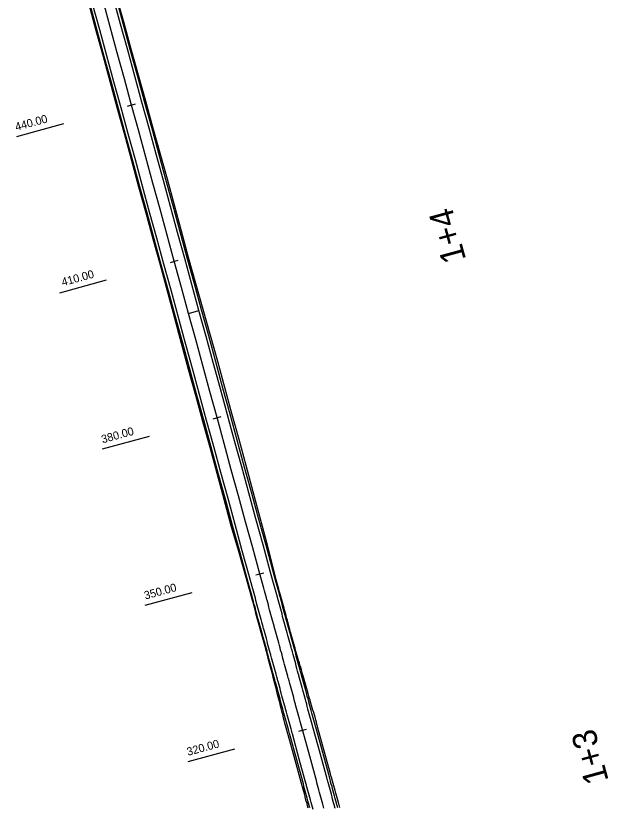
# Model space of a CAD drawing. Extents: x -550605 to -538780, y -1102367 to -1093705.
# Drawn here: x -547439.5 to -547329.7, y -1100950.2 to -1100803.7 of the extents above; entities that cross this region are included whole.
import ezdxf

# ---------------------------------------------------------------- set-up
doc = ezdxf.new("R2010")
doc.units = 0
for name, color, linetype in [('SIT - hrany vozovky', 7, 'Continuous'), ('SIT - osa cesty', 7, 'Continuous'), ('SIT - paty násypů', 7, 'Continuous'), ('SIT - staničení po 100m', 7, 'Continuous'), ('SIT - staničení po 30m', 7, 'Continuous')]:
    doc.layers.add(name, color=color, linetype=linetype)

msp = doc.modelspace()

# ---------------------------------------------------------------- linework, layer by layer
at = {"layer": 'SIT - hrany vozovky'}
for points in [[(-547380.29, -1100950.47), (-547380.41, -1100950.03), (-547380.45, -1100949.88), (-547380.53, -1100949.58), (-547380.65, -1100949.14), (-547380.77, -1100948.7), (-547380.89, -1100948.26), (-547381.01, -1100947.82), (-547381.13, -1100947.37), (-547381.26, -1100946.93), (-547381.38, -1100946.49), (-547381.5, -1100946.05), (-547381.62, -1100945.61), (-547381.74, -1100945.17), (-547381.77, -1100945.06), (-547381.86, -1100944.72), (-547381.98, -1100944.28), (-547383.09, -1100940.23), (-547384.37, -1100935.55), (-547384.41, -1100935.41), (-547384.49, -1100935.11), (-547384.61, -1100934.67), (-547384.73, -1100934.23), (-547384.85, -1100933.79), (-547384.97, -1100933.35), (-547385.09, -1100932.91), (-547385.22, -1100932.47), (-547385.34, -1100932.03), (-547385.46, -1100931.59), (-547385.58, -1100931.15), (-547385.7, -1100930.71), (-547385.73, -1100930.59), (-547385.82, -1100930.27), (-547385.94, -1100929.83), (-547386.06, -1100929.39), (-547386.18, -1100928.95), (-547386.3, -1100928.51), (-547386.42, -1100928.07), (-547386.54, -1100927.63), (-547386.66, -1100927.19), (-547386.78, -1100926.75), (-547386.9, -1100926.31), (-547387.02, -1100925.87), (-547387.05, -1100925.77), (-547387.14, -1100925.43), (-547387.26, -1100924.99), (-547387.38, -1100924.55), (-547387.5, -1100924.11), (-547387.62, -1100923.67), (-547387.74, -1100923.23), (-547387.86, -1100922.79), (-547387.98, -1100922.35), (-547388.1, -1100921.91), (-547388.23, -1100921.47), (-547388.35, -1100921.03), (-547388.37, -1100920.94), (-547388.47, -1100920.59), (-547388.59, -1100920.15), (-547388.71, -1100919.71), (-547388.83, -1100919.27), (-547388.95, -1100918.83), (-547389.07, -1100918.39), (-547389.19, -1100917.95), (-547389.31, -1100917.51), (-547389.43, -1100917.07), (-547389.55, -1100916.63), (-547389.67, -1100916.19), (-547389.69, -1100916.12), (-547389.79, -1100915.75), (-547389.91, -1100915.31), (-547390.03, -1100914.87), (-547390.15, -1100914.43), (-547390.27, -1100913.99), (-547390.39, -1100913.55), (-547390.51, -1100913.11), (-547390.63, -1100912.67), (-547390.75, -1100912.23), (-547390.87, -1100911.79), (-547390.99, -1100911.35), (-547391.01, -1100911.3), (-547391.12, -1100910.91), (-547391.24, -1100910.47), (-547391.36, -1100910.03), (-547391.48, -1100909.59), (-547391.6, -1100909.15), (-547391.72, -1100908.71), (-547391.84, -1100908.27), (-547392.33, -1100906.48), (-547393.65, -1100901.65), (-547394.97, -1100896.83), (-547396.29, -1100892.01), (-547397.61, -1100887.18), (-547398.93, -1100882.36), (-547400.25, -1100877.54), (-547401.57, -1100872.72), (-547402.89, -1100867.89), (-547404.21, -1100863.07), (-547405.53, -1100858.25), (-547406.85, -1100853.43), (-547408.17, -1100848.6), (-547409.49, -1100843.78), (-547410.81, -1100838.96), (-547412.13, -1100834.14), (-547413.45, -1100829.31), (-547414.77, -1100824.49), (-547416.09, -1100819.67), (-547417.41, -1100814.85), (-547418.73, -1100810.02), (-547420.05, -1100805.2), (-547421.37, -1100800.38)], [(-547379.81, -1100950.34), (-547379.93, -1100949.89), (-547379.97, -1100949.75), (-547380.05, -1100949.45), (-547380.17, -1100949.01), (-547380.29, -1100948.57), (-547380.41, -1100948.13), (-547380.53, -1100947.68), (-547380.65, -1100947.24), (-547380.77, -1100946.8), (-547380.89, -1100946.36), (-547381.02, -1100945.92), (-547381.14, -1100945.48), (-547381.26, -1100945.03), (-547381.29, -1100944.92), (-547381.38, -1100944.59), (-547381.5, -1100944.15), (-547382.61, -1100940.1), (-547383.89, -1100935.41), (-547383.93, -1100935.28), (-547384.01, -1100934.97), (-547384.13, -1100934.53), (-547384.25, -1100934.09), (-547384.37, -1100933.65), (-547384.49, -1100933.21), (-547384.61, -1100932.77), (-547384.73, -1100932.33), (-547384.85, -1100931.89), (-547384.97, -1100931.45), (-547385.09, -1100931.01), (-547385.21, -1100930.57), (-547385.25, -1100930.46), (-547385.33, -1100930.14), (-547385.46, -1100929.7), (-547385.58, -1100929.26), (-547385.7, -1100928.82), (-547385.82, -1100928.38), (-547385.94, -1100927.94), (-547386.06, -1100927.5), (-547386.18, -1100927.06), (-547386.3, -1100926.62), (-547386.42, -1100926.18), (-547386.54, -1100925.74), (-547386.57, -1100925.63), (-547386.66, -1100925.3), (-547386.78, -1100924.86), (-547386.9, -1100924.42), (-547387.02, -1100923.98), (-547387.14, -1100923.54), (-547387.26, -1100923.1), (-547387.38, -1100922.66), (-547387.5, -1100922.22), (-547387.62, -1100921.78), (-547387.74, -1100921.34), (-547387.86, -1100920.9), (-547387.89, -1100920.81), (-547387.98, -1100920.46), (-547388.1, -1100920.02), (-547388.22, -1100919.58), (-547388.35, -1100919.14), (-547388.47, -1100918.7), (-547388.59, -1100918.26), (-547388.71, -1100917.82), (-547388.83, -1100917.38), (-547388.95, -1100916.94), (-547389.07, -1100916.5), (-547389.19, -1100916.06), (-547389.21, -1100915.99), (-547389.31, -1100915.62), (-547389.43, -1100915.18), (-547389.55, -1100914.74), (-547389.67, -1100914.3), (-547389.79, -1100913.86), (-547389.91, -1100913.42), (-547390.03, -1100912.98), (-547390.15, -1100912.54), (-547390.27, -1100912.1), (-547390.39, -1100911.66), (-547390.51, -1100911.22), (-547390.53, -1100911.17), (-547390.63, -1100910.78), (-547390.75, -1100910.34), (-547390.87, -1100909.9), (-547390.99, -1100909.46), (-547391.11, -1100909.02), (-547391.24, -1100908.58), (-547391.36, -1100908.14), (-547391.85, -1100906.34), (-547393.17, -1100901.52), (-547394.49, -1100896.7), (-547395.81, -1100891.88), (-547397.13, -1100887.05), (-547398.45, -1100882.23), (-547399.77, -1100877.41), (-547401.09, -1100872.59), (-547402.41, -1100867.76), (-547403.73, -1100862.94), (-547405.05, -1100858.12), (-547406.37, -1100853.29), (-547407.69, -1100848.47), (-547409.01, -1100843.65), (-547410.33, -1100838.83), (-547411.65, -1100834), (-547412.97, -1100829.18), (-547414.29, -1100824.36), (-547415.61, -1100819.54), (-547416.93, -1100814.71), (-547418.25, -1100809.89), (-547419.57, -1100805.07), (-547420.89, -1100800.25)], [(-547384.99, -1100950.33), (-547385.11, -1100949.89), (-547385.23, -1100949.45), (-547385.35, -1100949), (-547385.48, -1100948.56), (-547385.6, -1100948.12), (-547385.72, -1100947.68), (-547385.84, -1100947.24), (-547385.96, -1100946.8), (-547386.08, -1100946.35), (-547386.11, -1100946.24), (-547386.2, -1100945.91), (-547386.32, -1100945.47), (-547387.43, -1100941.42), (-547388.71, -1100936.73), (-547388.75, -1100936.6), (-547388.83, -1100936.29), (-547388.95, -1100935.85), (-547389.07, -1100935.41), (-547389.19, -1100934.97), (-547389.31, -1100934.53), (-547389.43, -1100934.09), (-547389.56, -1100933.65), (-547389.68, -1100933.21), (-547389.8, -1100932.77), (-547389.92, -1100932.33), (-547390.04, -1100931.89), (-547390.07, -1100931.78), (-547390.16, -1100931.45), (-547390.28, -1100931.01), (-547390.4, -1100930.57), (-547390.52, -1100930.14), (-547390.64, -1100929.7), (-547390.76, -1100929.26), (-547390.88, -1100928.82), (-547391, -1100928.38), (-547391.12, -1100927.94), (-547391.24, -1100927.5), (-547391.36, -1100927.06), (-547391.39, -1100926.95), (-547391.48, -1100926.62), (-547391.6, -1100926.18), (-547391.72, -1100925.74), (-547391.84, -1100925.3), (-547391.96, -1100924.86), (-547392.08, -1100924.42), (-547392.2, -1100923.98), (-547392.32, -1100923.54), (-547392.45, -1100923.1), (-547392.57, -1100922.66), (-547392.69, -1100922.22), (-547392.71, -1100922.13), (-547392.81, -1100921.78), (-547392.93, -1100921.34), (-547393.05, -1100920.9), (-547393.17, -1100920.46), (-547393.29, -1100920.02), (-547393.41, -1100919.58), (-547393.53, -1100919.14), (-547393.65, -1100918.7), (-547393.77, -1100918.26), (-547393.89, -1100917.82), (-547394.01, -1100917.38), (-547394.03, -1100917.31), (-547394.13, -1100916.94), (-547394.25, -1100916.5), (-547394.37, -1100916.06), (-547394.49, -1100915.62), (-547394.61, -1100915.18), (-547394.73, -1100914.74), (-547394.85, -1100914.3), (-547394.97, -1100913.86), (-547395.09, -1100913.42), (-547395.21, -1100912.98), (-547395.34, -1100912.54), (-547395.35, -1100912.49), (-547395.46, -1100912.1), (-547395.58, -1100911.66), (-547395.7, -1100911.22), (-547395.82, -1100910.78), (-547395.94, -1100910.34), (-547396.06, -1100909.9), (-547396.18, -1100909.46), (-547396.67, -1100907.66), (-547397.99, -1100902.84), (-547399.31, -1100898.02), (-547400.63, -1100893.2), (-547401.95, -1100888.37), (-547403.27, -1100883.55), (-547404.59, -1100878.73), (-547405.91, -1100873.9), (-547407.23, -1100869.08), (-547408.55, -1100864.26), (-547409.87, -1100859.44), (-547411.19, -1100854.61), (-547412.51, -1100849.79), (-547413.83, -1100844.97), (-547415.15, -1100840.15), (-547416.47, -1100835.32), (-547417.79, -1100830.5), (-547419.11, -1100825.68), (-547420.43, -1100820.86), (-547421.75, -1100816.03), (-547423.07, -1100811.21), (-547424.39, -1100806.39), (-547425.71, -1100801.57)], [(-547384.39, -1100950.64), (-547384.51, -1100950.2), (-547384.63, -1100949.76), (-547384.75, -1100949.31), (-547384.87, -1100948.87), (-547384.99, -1100948.43), (-547385.11, -1100947.99), (-547385.23, -1100947.55), (-547385.36, -1100947.11), (-547385.48, -1100946.66), (-547385.6, -1100946.22), (-547385.63, -1100946.11), (-547385.72, -1100945.78), (-547385.84, -1100945.34), (-547386.95, -1100941.29), (-547388.23, -1100936.6), (-547388.27, -1100936.47), (-547388.35, -1100936.16), (-547388.47, -1100935.72), (-547388.59, -1100935.28), (-547388.71, -1100934.84), (-547388.83, -1100934.4), (-547388.95, -1100933.96), (-547389.07, -1100933.52), (-547389.19, -1100933.08), (-547389.31, -1100932.64), (-547389.43, -1100932.2), (-547389.55, -1100931.76), (-547389.59, -1100931.64), (-547389.68, -1100931.32), (-547389.8, -1100930.88), (-547389.92, -1100930.44), (-547390.04, -1100930), (-547390.16, -1100929.56), (-547390.28, -1100929.12), (-547390.4, -1100928.68), (-547390.52, -1100928.24), (-547390.64, -1100927.8), (-547390.76, -1100927.36), (-547390.88, -1100926.92), (-547390.91, -1100926.82), (-547391, -1100926.48), (-547391.12, -1100926.04), (-547391.24, -1100925.6), (-547391.36, -1100925.16), (-547391.48, -1100924.72), (-547391.6, -1100924.28), (-547391.72, -1100923.84), (-547391.84, -1100923.4), (-547391.96, -1100922.96), (-547392.08, -1100922.52), (-547392.2, -1100922.08), (-547392.23, -1100922), (-547392.32, -1100921.64), (-547392.44, -1100921.2), (-547392.57, -1100920.76), (-547392.69, -1100920.32), (-547392.81, -1100919.88), (-547392.93, -1100919.44), (-547393.05, -1100919), (-547393.17, -1100918.56), (-547393.29, -1100918.12), (-547393.41, -1100917.68), (-547393.53, -1100917.24), (-547393.55, -1100917.18), (-547393.65, -1100916.8), (-547393.77, -1100916.36), (-547393.89, -1100915.92), (-547394.01, -1100915.48), (-547394.13, -1100915.04), (-547394.25, -1100914.6), (-547394.37, -1100914.16), (-547394.49, -1100913.72), (-547394.61, -1100913.28), (-547394.73, -1100912.84), (-547394.85, -1100912.4), (-547394.87, -1100912.35), (-547394.97, -1100911.96), (-547395.09, -1100911.52), (-547395.21, -1100911.08), (-547395.33, -1100910.64), (-547395.46, -1100910.21), (-547395.58, -1100909.77), (-547395.7, -1100909.33), (-547396.19, -1100907.53), (-547397.51, -1100902.71), (-547398.83, -1100897.89), (-547400.15, -1100893.06), (-547401.47, -1100888.24), (-547402.79, -1100883.42), (-547404.11, -1100878.6), (-547405.43, -1100873.77), (-547406.75, -1100868.95), (-547408.07, -1100864.13), (-547409.39, -1100859.31), (-547410.71, -1100854.48), (-547412.03, -1100849.66), (-547413.35, -1100844.84), (-547414.67, -1100840.01), (-547415.99, -1100835.19), (-547417.31, -1100830.37), (-547418.63, -1100825.55), (-547419.95, -1100820.72), (-547421.27, -1100815.9), (-547422.59, -1100811.08), (-547423.91, -1100806.26), (-547425.23, -1100801.43)]]:
    msp.add_lwpolyline(points, dxfattribs=at)
at = {"layer": 'SIT - osa cesty'}
msp.add_lwpolyline([(-547382.38, -1100950.41), (-547382.46, -1100950.11), (-547382.58, -1100949.67), (-547382.7, -1100949.23), (-547382.82, -1100948.79), (-547382.94, -1100948.34), (-547383.06, -1100947.9), (-547383.18, -1100947.46), (-547383.31, -1100947.02), (-547383.43, -1100946.58), (-547383.55, -1100946.14), (-547383.67, -1100945.69), (-547383.7, -1100945.58), (-547383.79, -1100945.25), (-547383.91, -1100944.81), (-547385.02, -1100940.76), (-547386.3, -1100936.07), (-547386.34, -1100935.94), (-547386.42, -1100935.63), (-547386.54, -1100935.19), (-547386.66, -1100934.75), (-547386.78, -1100934.31), (-547386.9, -1100933.87), (-547387.02, -1100933.43), (-547387.14, -1100932.99), (-547387.26, -1100932.55), (-547387.38, -1100932.11), (-547387.51, -1100931.67), (-547387.63, -1100931.23), (-547387.66, -1100931.12), (-547387.75, -1100930.79), (-547387.87, -1100930.35), (-547387.99, -1100929.92), (-547388.11, -1100929.48), (-547388.23, -1100929.04), (-547388.35, -1100928.6), (-547388.47, -1100928.16), (-547388.59, -1100927.72), (-547388.71, -1100927.28), (-547388.83, -1100926.84), (-547388.95, -1100926.4), (-547388.98, -1100926.29), (-547389.07, -1100925.96), (-547389.19, -1100925.52), (-547389.31, -1100925.08), (-547389.43, -1100924.64), (-547389.55, -1100924.2), (-547389.67, -1100923.76), (-547389.79, -1100923.32), (-547389.91, -1100922.88), (-547390.03, -1100922.44), (-547390.15, -1100922), (-547390.27, -1100921.56), (-547390.3, -1100921.47), (-547390.4, -1100921.12), (-547390.52, -1100920.68), (-547390.64, -1100920.24), (-547390.76, -1100919.8), (-547390.88, -1100919.36), (-547391, -1100918.92), (-547391.12, -1100918.48), (-547391.24, -1100918.04), (-547391.36, -1100917.6), (-547391.48, -1100917.16), (-547391.6, -1100916.72), (-547391.62, -1100916.65), (-547391.72, -1100916.28), (-547391.84, -1100915.84), (-547391.96, -1100915.4), (-547392.08, -1100914.96), (-547392.2, -1100914.52), (-547392.32, -1100914.08), (-547392.44, -1100913.64), (-547392.56, -1100913.2), (-547392.68, -1100912.76), (-547392.8, -1100912.32), (-547392.92, -1100911.88), (-547392.94, -1100911.83), (-547393.04, -1100911.44), (-547393.16, -1100911), (-547393.29, -1100910.56), (-547393.41, -1100910.12), (-547393.53, -1100909.68), (-547393.65, -1100909.24), (-547393.77, -1100908.8), (-547394.26, -1100907), (-547395.58, -1100902.18), (-547396.9, -1100897.36), (-547398.22, -1100892.54), (-547399.54, -1100887.71), (-547400.86, -1100882.89), (-547402.18, -1100878.07), (-547403.5, -1100873.24), (-547404.82, -1100868.42), (-547406.14, -1100863.6), (-547407.46, -1100858.78), (-547408.78, -1100853.95), (-547410.1, -1100849.13), (-547411.42, -1100844.31), (-547412.74, -1100839.49), (-547414.06, -1100834.66), (-547415.38, -1100829.84), (-547416.7, -1100825.02), (-547418.02, -1100820.2), (-547419.34, -1100815.37), (-547420.66, -1100810.55), (-547421.98, -1100805.73), (-547423.3, -1100800.91)], dxfattribs=at)
at = {"layer": 'SIT - paty násypů'}
for points in [[(-547379.44, -1100950.24), (-547379.56, -1100949.79), (-547379.6, -1100949.65), (-547379.68, -1100949.35), (-547379.8, -1100948.91), (-547379.92, -1100948.47), (-547380.05, -1100948.03), (-547380.17, -1100947.59), (-547380.29, -1100947.14), (-547380.41, -1100946.7), (-547380.53, -1100946.26), (-547380.66, -1100945.82), (-547380.78, -1100945.38), (-547380.9, -1100944.94), (-547380.93, -1100944.83), (-547381.02, -1100944.5), (-547381.15, -1100944.05), (-547382.28, -1100940.01), (-547383.56, -1100935.32), (-547383.59, -1100935.19), (-547383.68, -1100934.88), (-547383.79, -1100934.44), (-547383.91, -1100934), (-547384.03, -1100933.56), (-547384.15, -1100933.12), (-547384.28, -1100932.68), (-547384.41, -1100932.25), (-547384.54, -1100931.81), (-547384.66, -1100931.37), (-547384.79, -1100930.93), (-547384.92, -1100930.49), (-547384.95, -1100930.38), (-547385.05, -1100930.06), (-547385.18, -1100929.62), (-547385.3, -1100929.18), (-547385.43, -1100928.74), (-547385.56, -1100928.3), (-547385.68, -1100927.87), (-547385.81, -1100927.43), (-547385.94, -1100926.99), (-547386.06, -1100926.55), (-547386.19, -1100926.11), (-547386.32, -1100925.67), (-547386.35, -1100925.57), (-547386.44, -1100925.24), (-547386.57, -1100924.8), (-547386.69, -1100924.36), (-547386.82, -1100923.92), (-547386.94, -1100923.48), (-547387.07, -1100923.04), (-547387.19, -1100922.6), (-547387.32, -1100922.17), (-547387.44, -1100921.73), (-547387.57, -1100921.29), (-547387.69, -1100920.85), (-547387.71, -1100920.76), (-547387.81, -1100920.41), (-547387.94, -1100919.97), (-547388.06, -1100919.53), (-547388.18, -1100919.09), (-547388.31, -1100918.65), (-547388.43, -1100918.21), (-547388.55, -1100917.77), (-547388.68, -1100917.33), (-547388.8, -1100916.9), (-547388.92, -1100916.46), (-547389.04, -1100916.02), (-547389.06, -1100915.95), (-547389.16, -1100915.58), (-547389.29, -1100915.14), (-547389.41, -1100914.7), (-547389.53, -1100914.26), (-547389.65, -1100913.82), (-547389.77, -1100913.38), (-547389.89, -1100912.94), (-547390.01, -1100912.5), (-547390.13, -1100912.06), (-547390.25, -1100911.62), (-547390.37, -1100911.18), (-547390.39, -1100911.13), (-547390.49, -1100910.74), (-547390.61, -1100910.3), (-547390.73, -1100909.86), (-547390.85, -1100909.42), (-547390.97, -1100908.98), (-547391.09, -1100908.54), (-547391.21, -1100908.1), (-547391.68, -1100906.3), (-547392.92, -1100901.45), (-547394.19, -1100896.62), (-547395.49, -1100891.79), (-547396.8, -1100886.96), (-547398.11, -1100882.14), (-547399.42, -1100877.31), (-547400.72, -1100872.49), (-547402.04, -1100867.66), (-547403.39, -1100862.85), (-547404.76, -1100858.04), (-547406.12, -1100853.23), (-547407.44, -1100848.4), (-547408.75, -1100843.58), (-547410.07, -1100838.76), (-547411.38, -1100833.93), (-547412.72, -1100829.11), (-547414.06, -1100824.3), (-547415.4, -1100819.48), (-547416.74, -1100814.66), (-547418.08, -1100809.84), (-547419.41, -1100805.03), (-547420.75, -1100800.21)], [(-547385.28, -1100950.41), (-547385.4, -1100949.97), (-547385.52, -1100949.53), (-547385.65, -1100949.08), (-547385.77, -1100948.64), (-547385.89, -1100948.2), (-547386, -1100947.76), (-547386.12, -1100947.32), (-547386.24, -1100946.87), (-547386.36, -1100946.43), (-547386.39, -1100946.32), (-547386.48, -1100945.99), (-547386.6, -1100945.55), (-547387.72, -1100941.5), (-547389.01, -1100936.82), (-547389.05, -1100936.68), (-547389.13, -1100936.38), (-547389.25, -1100935.94), (-547389.37, -1100935.5), (-547389.5, -1100935.06), (-547389.62, -1100934.62), (-547389.74, -1100934.18), (-547389.85, -1100933.73), (-547389.96, -1100933.29), (-547390.07, -1100932.85), (-547390.18, -1100932.41), (-547390.29, -1100931.96), (-547390.32, -1100931.85), (-547390.4, -1100931.52), (-547390.52, -1100931.08), (-547390.63, -1100930.64), (-547390.74, -1100930.2), (-547390.85, -1100929.75), (-547390.97, -1100929.31), (-547391.08, -1100928.87), (-547391.19, -1100928.43), (-547391.31, -1100927.99), (-547391.42, -1100927.54), (-547391.53, -1100927.1), (-547391.56, -1100927), (-547391.65, -1100926.66), (-547391.76, -1100926.22), (-547391.88, -1100925.78), (-547391.99, -1100925.34), (-547392.11, -1100924.89), (-547392.22, -1100924.45), (-547392.34, -1100924.01), (-547392.45, -1100923.57), (-547392.57, -1100923.13), (-547392.69, -1100922.69), (-547392.8, -1100922.25), (-547392.82, -1100922.16), (-547392.92, -1100921.81), (-547393.03, -1100921.37), (-547393.15, -1100920.92), (-547393.27, -1100920.48), (-547393.39, -1100920.04), (-547393.51, -1100919.6), (-547393.63, -1100919.16), (-547393.76, -1100918.73), (-547393.88, -1100918.29), (-547394, -1100917.85), (-547394.12, -1100917.41), (-547394.14, -1100917.34), (-547394.24, -1100916.97), (-547394.36, -1100916.53), (-547394.49, -1100916.09), (-547394.61, -1100915.65), (-547394.73, -1100915.21), (-547394.85, -1100914.77), (-547394.97, -1100914.33), (-547395.08, -1100913.89), (-547395.2, -1100913.45), (-547395.32, -1100913.01), (-547395.44, -1100912.57), (-547395.45, -1100912.51), (-547395.56, -1100912.12), (-547395.68, -1100911.68), (-547395.8, -1100911.24), (-547395.91, -1100910.8), (-547396.03, -1100910.36), (-547396.15, -1100909.92), (-547396.27, -1100909.48), (-547396.76, -1100907.69), (-547398.16, -1100902.89), (-547399.55, -1100898.08), (-547400.86, -1100893.26), (-547402.17, -1100888.43), (-547403.47, -1100883.61), (-547404.8, -1100878.78), (-547406.12, -1100873.96), (-547407.45, -1100869.14), (-547408.77, -1100864.32), (-547410.08, -1100859.49), (-547411.35, -1100854.66), (-547412.65, -1100849.83), (-547413.99, -1100845.01), (-547415.33, -1100840.2), (-547416.67, -1100835.38), (-547417.98, -1100830.55), (-547419.29, -1100825.73), (-547420.6, -1100820.9), (-547421.92, -1100816.08), (-547423.23, -1100811.25), (-547424.56, -1100806.43), (-547425.89, -1100801.61)]]:
    msp.add_lwpolyline(points, dxfattribs=at)
at = {"layer": 'SIT - staničení po 100m'}
msp.add_lwpolyline([(-547407.46, -1100858.78), (-547405.53, -1100858.25)], dxfattribs=at)
at = {"layer": 'SIT - staničení po 30m'}
for points in [[(-547418.74, -1100820.39), (-547417.29, -1100820)], [(-547439.24, -1100826), (-547430.56, -1100823.63)], [(-547410.82, -1100849.33), (-547409.37, -1100848.93)], [(-547431.32, -1100854.94), (-547422.64, -1100852.56)], [(-547402.9, -1100878.27), (-547401.45, -1100877.87)], [(-547423.4, -1100883.88), (-547414.72, -1100881.5)], [(-547394.98, -1100907.2), (-547393.53, -1100906.81)], [(-547415.48, -1100912.81), (-547406.8, -1100910.44)], [(-547387.06, -1100936.14), (-547385.61, -1100935.74)], [(-547407.56, -1100941.75), (-547398.88, -1100939.37)]]:
    msp.add_lwpolyline(points, dxfattribs=at)

# ---------------------------------------------------------------- texts
at = {"layer": 'SIT - staničení po 100m'}
for s, p in [('1+4', (-547356.02, -1100848.8)), ('1+3', (-547329.61, -1100945.27))]:
    msp.add_text(s, height=4.5, rotation=105.307, dxfattribs=at).set_placement(p)
at = {"layer": 'SIT - staničení po 30m'}
for s, p in [('440.00', (-547439.37, -1100825)), ('410.00', (-547430.76, -1100853.75)), ('380.00', (-547423.39, -1100882.84)), ('350.00', (-547415.47, -1100911.77)), ('320.00', (-547407.56, -1100940.71))]:
    msp.add_text(s, height=1.5, rotation=15.307, dxfattribs=at).set_placement(p)

doc.saveas('drawing.dxf')
